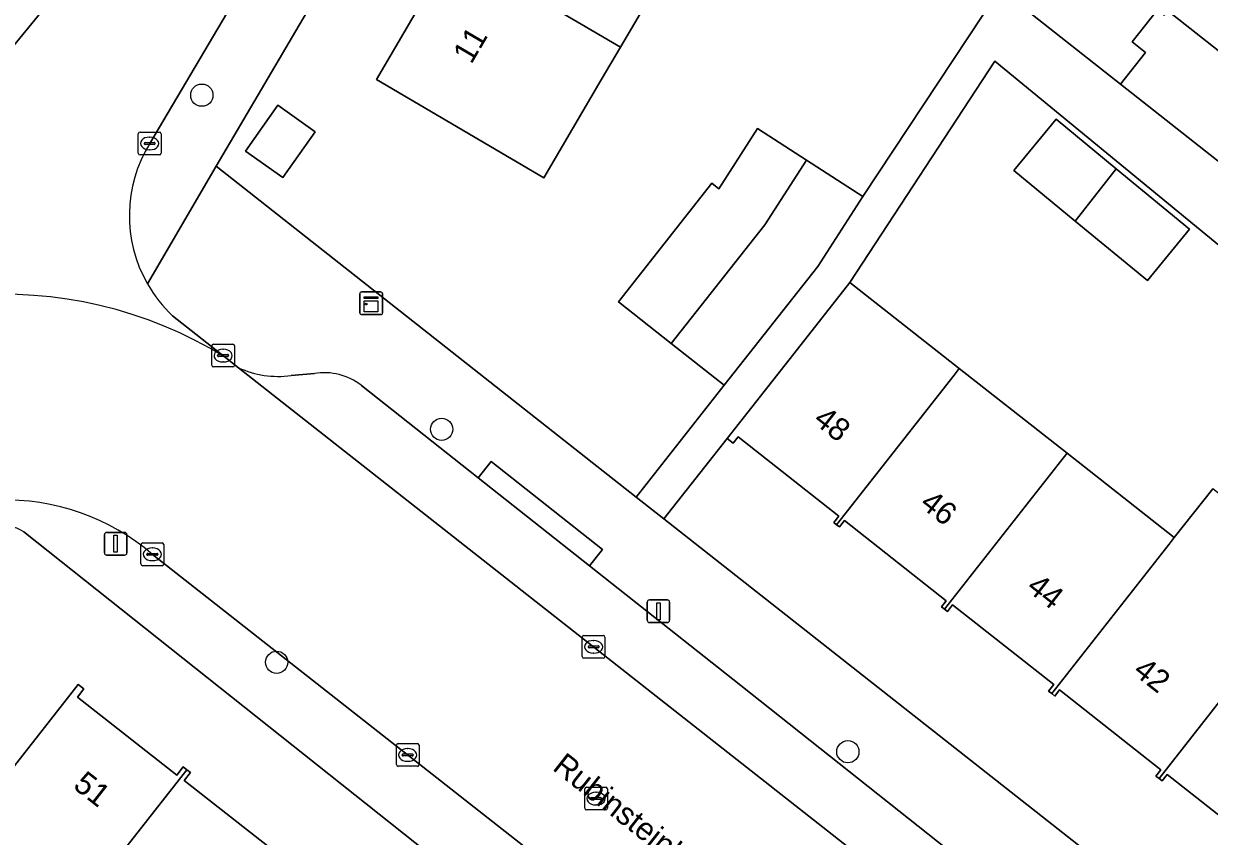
# Model space of a CAD drawing. Extents: x 159217 to 160349, y 381246 to 382172.
# Drawn here: x 160092 to 160144.2, y 381952.3 to 381988.1 of the extents above; entities that cross this region are included whole.
import ezdxf

# ---------------------------------------------------------------- set-up
doc = ezdxf.new("R2010")
doc.units = 0
for name, color, linetype in [('IMGEO_Boom', 7, 'Continuous'), ('IMGEO_Erf', 7, 'Continuous'), ('IMGEO_Kast', 7, 'Continuous'), ('IMGEO_Kolk', 7, 'Continuous'), ('IMGEO_Lichtmast', 7, 'Continuous'), ('IMGEO_Openbare_ruimte_label', 7, 'Continuous'), ('IMGEO_Pand', 7, 'Continuous'), ('IMGEO_Pand_nummerreeks', 7, 'Continuous'), ('IMGEO_Parkeervlak_open', 7, 'Continuous'), ('IMGEO_Rijbaan_lokaal_gesloten', 7, 'Continuous'), ('IMGEO_Rijbaan_lokaal_open', 7, 'Continuous'), ('IMGEO_Rioolput', 7, 'Continuous'), ('IMGEO_Voetpad_open', 7, 'Continuous')]:
    doc.layers.add(name, color=color, linetype=linetype)

msp = doc.modelspace()

# ---------------------------------------------------------------- linework, layer by layer
at = {"layer": 'IMGEO_Boom'}
for centre in [(160099.826, 381984.911), (160110.381, 381970.206), (160103.116, 381959.953), (160128.263, 381956.012)]:
    msp.add_circle(centre, 0.489, dxfattribs=at)
at = {"layer": 'IMGEO_Erf'}
for points in [[(160126.924, 382026.759), (160111.174, 382000), (160100.451, 381981.781), (160118.948, 381967.225), (160122.82, 381972.146), (160120.49, 381973.98), (160118.16, 381975.813), (160122.273, 381981.04), (160122.583, 381980.796), (160124.283, 381983.444), (160126.436, 381982.056), (160128.915, 381980.458), (160134.234, 381988.47), (160134.467, 381988.841), (160132.014, 381990.384), (160133.701, 381993.064), (160135.459, 381995.859)], [(160142.347, 381988.629), (160147.34, 381984.688)], [(160146.891, 381976.411), (160134.736, 381986.411), (160128.352, 381976.673), (160133.167, 381972.884), (160137.909, 381969.152), (160142.626, 381965.44), (160144.323, 381967.591)], [(160146.725, 381951.543), (160142.32, 381955.01), (160142.097, 381954.727), (160141.958, 381954.836), (160141.822, 381954.943), (160142.04, 381955.219), (160137.577, 381958.731), (160137.369, 381958.466), (160137.235, 381958.572), (160137.099, 381958.679), (160137.326, 381958.967), (160132.872, 381962.473), (160132.647, 381962.186), (160132.516, 381962.289), (160132.386, 381962.392), (160132.595, 381962.658), (160128.11, 381966.187), (160127.889, 381965.907), (160127.765, 381966.005), (160127.639, 381966.104), (160127.86, 381966.385), (160123.434, 381969.867), (160123.219, 381969.593), (160122.949, 381969.806), (160120.164, 381966.268), (160212.178, 381893.858)], [(160135.047, 381931.474), (160091.985, 381965.697)], [(160087.516, 381950.232), (160089.231, 381952.418), (160094.379, 381958.975)], [(160094.379, 381958.975), (160094.63, 381958.778), (160094.351, 381958.422), (160098.729, 381954.986), (160099.01, 381955.344), (160099.168, 381955.22), (160099.323, 381955.098), (160099.05, 381954.749), (160103.465, 381951.284)]]:
    msp.add_lwpolyline(points, dxfattribs=at)
for points in [[(160118.255, 381987.024), (160117.408, 381985.582), (160114.88, 381981.268), (160107.512, 381985.605), (160110.881, 381991.35), (160114.176, 381996.967), (160115.955, 382000), (160117.471, 382002.584), (160120.765, 382008.2), (160124.08, 382013.852), (160127.432, 382019.567), (160131.914, 382016.929), (160133.752, 382020.052), (160139.591, 382015.557), (160137.882, 382012.653), (160134.482, 382014.654), (160131.509, 382009.591), (160128.149, 382003.87), (160125.876, 382000), (160124.851, 381998.255), (160121.553, 381992.64)], [(160103.394, 381981.281), (160101.747, 381982.443), (160103.174, 381984.466), (160104.821, 381983.304)], [(160135.57, 381981.592), (160137.425, 381983.849), (160140.075, 381981.67), (160143.306, 381979.014), (160141.45, 381976.758), (160138.27, 381979.372)]]:
    msp.add_lwpolyline(points, close=True, dxfattribs=at)
msp.add_arc((160090.828, 381963.741), 2.273, 59.4048, 126.484, dxfattribs=at)
at = {"layer": 'IMGEO_Kast'}
for p, q in [((160106.779, 381975.327), (160106.779, 381976.168)), ((160106.779, 381976.168), (160106.779, 381975.327)), ((160106.854, 381976.252), (160107.695, 381976.252)), ((160107.695, 381976.252), (160106.854, 381976.252)), ((160107.779, 381976.177), (160107.779, 381975.336)), ((160107.779, 381975.336), (160107.779, 381976.177)), ((160107.704, 381975.252), (160106.863, 381975.252)), ((160106.863, 381975.252), (160107.704, 381975.252))]:
    msp.add_line(p, q, dxfattribs=at)
for points in [[(160106.974, 381976.042), (160107.574, 381976.042), (160107.574, 381975.957), (160106.974, 381975.957), (160106.974, 381976.042)], [(160106.974, 381975.867), (160107.574, 381975.867), (160107.574, 381975.378), (160106.974, 381975.378), (160106.974, 381975.867)]]:
    msp.add_lwpolyline(points, dxfattribs=at)
msp.add_circle((160107.058, 381975.716), 0.0377, dxfattribs=at)
for centre, start, end in [((160106.857, 381976.174), 92.4484, 184.2845), ((160106.857, 381976.174), 92.4484, 184.2845), ((160107.701, 381976.174), 2.4484, 94.2845), ((160107.701, 381976.174), 2.4484, 94.2845), ((160106.857, 381975.33), 182.4484, 274.2845), ((160106.857, 381975.33), 182.4484, 274.2845), ((160107.701, 381975.33), 272.4484, 4.2845), ((160107.701, 381975.33), 272.4484, 4.2845)]:
    msp.add_arc(centre, 0.0779, start, end, dxfattribs=at)
at = {"layer": 'IMGEO_Kolk'}
for p, q in [((160097.029, 381982.358), (160097.029, 381983.21)), ((160097.104, 381983.284), (160097.956, 381983.284)), ((160097.517, 381983.064), (160097.542, 381983.064)), ((160098.03, 381983.21), (160098.03, 381982.358)), ((160097.288, 381982.778), (160097.288, 381982.79)), ((160097.726, 381982.741), (160097.328, 381982.741)), ((160097.331, 381982.827), (160097.729, 381982.827)), ((160097.54, 381982.504), (160097.515, 381982.504)), ((160097.772, 381982.79), (160097.772, 381982.778)), ((160097.956, 381982.284), (160097.104, 381982.284)), ((160100.263, 381973.023), (160100.263, 381973.875)), ((160100.338, 381973.949), (160101.19, 381973.949)), ((160100.565, 381973.492), (160100.963, 381973.492)), ((160100.751, 381973.729), (160100.776, 381973.729)), ((160101.264, 381973.875), (160101.264, 381973.023)), ((160100.522, 381973.443), (160100.522, 381973.455)), ((160100.96, 381973.406), (160100.562, 381973.406)), ((160100.774, 381973.169), (160100.749, 381973.169)), ((160101.006, 381973.455), (160101.006, 381973.443)), ((160101.19, 381972.949), (160100.338, 381972.949)), ((160097.147, 381964.277), (160097.147, 381965.129)), ((160097.222, 381965.203), (160098.074, 381965.203)), ((160098.148, 381965.129), (160098.148, 381964.277)), ((160097.406, 381964.697), (160097.406, 381964.709)), ((160097.844, 381964.66), (160097.446, 381964.66)), ((160097.449, 381964.746), (160097.847, 381964.746)), ((160097.635, 381964.983), (160097.66, 381964.983)), ((160097.89, 381964.709), (160097.89, 381964.697)), ((160098.074, 381964.203), (160097.222, 381964.203)), ((160097.658, 381964.423), (160097.633, 381964.423)), ((160116.57, 381960.204), (160116.57, 381961.056)), ((160116.645, 381961.13), (160117.497, 381961.13)), ((160117.571, 381961.056), (160117.571, 381960.204)), ((160116.829, 381960.624), (160116.829, 381960.636)), ((160117.267, 381960.587), (160116.869, 381960.587)), ((160116.872, 381960.673), (160117.27, 381960.673)), ((160117.058, 381960.91), (160117.083, 381960.91)), ((160117.313, 381960.636), (160117.313, 381960.624)), ((160117.497, 381960.13), (160116.645, 381960.13)), ((160117.081, 381960.35), (160117.056, 381960.35)), ((160108.387, 381955.445), (160108.387, 381956.297)), ((160108.462, 381956.371), (160109.314, 381956.371)), ((160109.388, 381956.297), (160109.388, 381955.445)), ((160108.646, 381955.865), (160108.646, 381955.877)), ((160109.084, 381955.828), (160108.686, 381955.828)), ((160108.689, 381955.914), (160109.087, 381955.914)), ((160108.875, 381956.151), (160108.9, 381956.151)), ((160109.13, 381955.877), (160109.13, 381955.865)), ((160109.314, 381955.371), (160108.462, 381955.371)), ((160108.898, 381955.591), (160108.873, 381955.591))]:
    msp.add_line(p, q, dxfattribs=at)
for points in [[(160097.029, 381982.358), (160097.029, 381983.21)], [(160097.104, 381983.284), (160097.956, 381983.284)], [(160098.03, 381983.21), (160098.03, 381982.358)], [(160097.956, 381982.284), (160097.104, 381982.284)], [(160100.263, 381973.023), (160100.263, 381973.875)], [(160100.338, 381973.949), (160101.19, 381973.949)], [(160101.264, 381973.875), (160101.264, 381973.023)], [(160101.19, 381972.949), (160100.338, 381972.949)], [(160097.147, 381964.277), (160097.147, 381965.129)], [(160097.222, 381965.203), (160098.074, 381965.203)], [(160098.148, 381965.129), (160098.148, 381964.277)], [(160098.074, 381964.203), (160097.222, 381964.203)], [(160116.57, 381960.204), (160116.57, 381961.056)], [(160116.645, 381961.13), (160117.497, 381961.13)], [(160117.571, 381961.056), (160117.571, 381960.204)], [(160117.497, 381960.13), (160116.645, 381960.13)], [(160108.387, 381955.445), (160108.387, 381956.297)], [(160108.462, 381956.371), (160109.314, 381956.371)], [(160109.388, 381956.297), (160109.388, 381955.445)], [(160109.314, 381955.371), (160108.462, 381955.371)]]:
    msp.add_lwpolyline(points, dxfattribs=at)
for centre, radius, start, end in [((160097.106, 381983.208), 0.0765, 91.552, 178.448), ((160097.106, 381983.208), 0.0765, 91.552, 178.448), ((160097.954, 381983.208), 0.0765, 1.552, 88.448), ((160097.954, 381983.208), 0.0765, 1.552, 88.448), ((160097.106, 381982.36), 0.0765, 181.552, 268.448), ((160097.106, 381982.36), 0.0765, 181.552, 268.448), ((160097.328, 381982.787), 0.0403, 85.8775, 175.7526), ((160097.325, 381982.777), 0.0366, 178.938, 274.7102), ((160097.729, 381982.784), 0.043, 264.8664, 352.4533), ((160097.733, 381982.789), 0.0386, 1.7309, 96.639), ((160097.954, 381982.36), 0.0765, 271.552, 358.448), ((160097.954, 381982.36), 0.0765, 271.552, 358.448), ((160100.34, 381973.873), 0.0765, 91.552, 178.448), ((160100.34, 381973.873), 0.0765, 91.552, 178.448), ((160100.562, 381973.452), 0.0403, 85.8775, 175.7526), ((160100.967, 381973.454), 0.0386, 1.7309, 96.639), ((160101.188, 381973.873), 0.0765, 1.552, 88.448), ((160101.188, 381973.873), 0.0765, 1.552, 88.448), ((160100.34, 381973.025), 0.0765, 181.552, 268.448), ((160100.34, 381973.025), 0.0765, 181.552, 268.448), ((160100.559, 381973.442), 0.0366, 178.938, 274.7102), ((160100.963, 381973.449), 0.043, 264.8664, 352.4533), ((160101.188, 381973.025), 0.0765, 271.552, 358.448), ((160101.188, 381973.025), 0.0765, 271.552, 358.448), ((160097.224, 381965.127), 0.0765, 91.552, 178.448), ((160097.224, 381965.127), 0.0765, 91.552, 178.448), ((160098.072, 381965.127), 0.0765, 1.552, 88.448), ((160098.072, 381965.127), 0.0765, 1.552, 88.448), ((160097.446, 381964.706), 0.0403, 85.8775, 175.7526), ((160097.443, 381964.696), 0.0366, 178.938, 274.7102), ((160097.847, 381964.703), 0.043, 264.8664, 352.4533), ((160097.851, 381964.708), 0.0386, 1.7309, 96.639), ((160097.224, 381964.279), 0.0765, 181.552, 268.448), ((160097.224, 381964.279), 0.0765, 181.552, 268.448), ((160098.072, 381964.279), 0.0765, 271.552, 358.448), ((160098.072, 381964.279), 0.0765, 271.552, 358.448), ((160116.647, 381961.054), 0.0765, 91.552, 178.448), ((160116.647, 381961.054), 0.0765, 91.552, 178.448), ((160117.495, 381961.054), 0.0765, 1.552, 88.448), ((160117.495, 381961.054), 0.0765, 1.552, 88.448), ((160116.869, 381960.633), 0.0403, 85.8775, 175.7526), ((160116.866, 381960.623), 0.0366, 178.938, 274.7102), ((160117.27, 381960.63), 0.043, 264.8664, 352.4533), ((160117.274, 381960.635), 0.0386, 1.7309, 96.639), ((160116.647, 381960.206), 0.0765, 181.552, 268.448), ((160116.647, 381960.206), 0.0765, 181.552, 268.448), ((160117.495, 381960.206), 0.0765, 271.552, 358.448), ((160117.495, 381960.206), 0.0765, 271.552, 358.448), ((160108.464, 381956.295), 0.0765, 91.552, 178.448), ((160108.464, 381956.295), 0.0765, 91.552, 178.448), ((160109.312, 381956.295), 0.0765, 1.552, 88.448), ((160109.312, 381956.295), 0.0765, 1.552, 88.448), ((160108.686, 381955.874), 0.0403, 85.8775, 175.7526), ((160108.683, 381955.864), 0.0366, 178.938, 274.7102), ((160109.087, 381955.871), 0.043, 264.8664, 352.4533), ((160109.091, 381955.876), 0.0386, 1.7309, 96.639), ((160108.464, 381955.447), 0.0765, 181.552, 268.448), ((160108.464, 381955.447), 0.0765, 181.552, 268.448), ((160109.312, 381955.447), 0.0765, 271.552, 358.448), ((160109.312, 381955.447), 0.0765, 271.552, 358.448)]:
    msp.add_arc(centre, radius, start, end, dxfattribs=at)
for centre, major_axis, ratio, start_param, end_param in [((160097.516, 381982.784), (-0.387, 0.002), 0.722429, 4.712389, 7.853982), ((160097.541, 381982.784), (-0.39, 0.002), 0.717154, 1.570796, 4.712389), ((160100.75, 381973.449), (-0.387, 0.002), 0.722429, 4.712389, 7.853982), ((160100.775, 381973.449), (-0.39, 0.002), 0.717154, 1.570796, 4.712389), ((160097.634, 381964.703), (-0.387, 0.002), 0.722429, 4.712389, 7.853982), ((160097.659, 381964.703), (-0.39, 0.002), 0.717154, 1.570796, 4.712389), ((160117.057, 381960.63), (-0.387, 0.002), 0.722429, 4.712389, 7.853982), ((160117.082, 381960.63), (-0.39, 0.002), 0.717154, 1.570796, 4.712389), ((160108.874, 381955.871), (-0.387, 0.002), 0.722429, 4.712389, 7.853982), ((160108.899, 381955.871), (-0.39, 0.002), 0.717154, 1.570796, 4.712389)]:
    msp.add_ellipse(centre, major_axis=major_axis, ratio=ratio, start_param=start_param, end_param=end_param, dxfattribs=at)
at = {"layer": 'IMGEO_Lichtmast'}
for p, q in [((160095.636, 381965.669), (160096.426, 381965.669)), ((160096.426, 381965.669), (160095.636, 381965.669)), ((160095.536, 381964.769), (160095.536, 381965.569)), ((160095.536, 381965.569), (160095.536, 381964.769)), ((160096.526, 381965.569), (160096.526, 381964.769)), ((160096.526, 381964.769), (160096.526, 381965.569)), ((160096.426, 381964.669), (160095.636, 381964.669)), ((160095.636, 381964.669), (160096.426, 381964.669)), ((160119.428, 381961.799), (160119.428, 381962.599)), ((160119.428, 381962.599), (160119.428, 381961.799)), ((160119.528, 381962.699), (160120.318, 381962.699)), ((160120.318, 381962.699), (160119.528, 381962.699)), ((160120.418, 381962.599), (160120.418, 381961.799)), ((160120.418, 381961.799), (160120.418, 381962.599)), ((160120.318, 381961.699), (160119.528, 381961.699)), ((160119.528, 381961.699), (160120.318, 381961.699))]:
    msp.add_line(p, q, dxfattribs=at)
for points in [[(160095.956, 381965.544), (160096.106, 381965.544), (160096.106, 381964.794), (160095.956, 381964.794), (160095.956, 381965.544)], [(160119.848, 381962.574), (160119.998, 381962.574), (160119.998, 381961.824), (160119.848, 381961.824), (160119.848, 381962.574)]]:
    msp.add_lwpolyline(points, dxfattribs=at)
for centre, start, end in [((160095.636, 381965.569), 90, 180), ((160095.636, 381965.569), 90, 180), ((160096.426, 381965.569), 0, 90), ((160096.426, 381965.569), 360, 90), ((160095.636, 381964.769), 180, 270), ((160095.636, 381964.769), 180, 270), ((160096.426, 381964.769), 270, 0), ((160096.426, 381964.769), 270, 0), ((160119.528, 381962.599), 90, 180), ((160119.528, 381962.599), 90, 180), ((160120.318, 381962.599), 0, 90), ((160120.318, 381962.599), 360, 90), ((160119.528, 381961.799), 180, 270), ((160119.528, 381961.799), 180, 270), ((160120.318, 381961.799), 270, 0), ((160120.318, 381961.799), 270, 0)]:
    msp.add_arc(centre, 0.1, start, end, dxfattribs=at)
at = {"layer": 'IMGEO_Pand'}
for points in [[(160118.255, 381987.024), (160121.553, 381992.64), (160114.176, 381996.967), (160110.881, 381991.35)], [(160140.263, 381985.397), (160141.368, 381986.793), (160140.78, 381987.259), (160141.89, 381988.662), (160142.184, 381988.429), (160142.347, 381988.629), (160142.24, 381988.714), (160142.971, 381989.64), (160138.933, 381992.828), (160136.182, 381988.616)], [(160118.255, 381987.024), (160110.881, 381991.35), (160107.512, 381985.605), (160114.88, 381981.268), (160117.408, 381985.582)], [(160140.263, 381985.397), (160144.969, 381981.684), (160147.34, 381984.688), (160142.347, 381988.629), (160142.184, 381988.429), (160141.89, 381988.662), (160140.78, 381987.259), (160141.368, 381986.793)], [(160101.747, 381982.443), (160103.394, 381981.281), (160104.821, 381983.304), (160103.174, 381984.466)], [(160124.605, 381979.205), (160126.436, 381982.056), (160124.283, 381983.444), (160122.583, 381980.796), (160122.273, 381981.04), (160118.16, 381975.813), (160120.49, 381973.98)], [(160140.075, 381981.67), (160137.425, 381983.849), (160135.57, 381981.592), (160138.27, 381979.372)], [(160120.49, 381973.98), (160122.82, 381972.146), (160126.933, 381977.373), (160128.915, 381980.458), (160126.436, 381982.056), (160124.605, 381979.205)], [(160140.075, 381981.67), (160138.27, 381979.372), (160141.45, 381976.758), (160143.306, 381979.014)], [(160127.765, 381966.005), (160132.935, 381972.584), (160133.167, 381972.884), (160128.352, 381976.673), (160126.041, 381973.736), (160122.949, 381969.806), (160123.219, 381969.593), (160123.434, 381969.867), (160127.86, 381966.385), (160127.639, 381966.104)], [(160137.909, 381969.152), (160133.167, 381972.884), (160132.935, 381972.584), (160127.765, 381966.005), (160127.889, 381965.907), (160128.11, 381966.187), (160132.595, 381962.658), (160132.386, 381962.392), (160132.516, 381962.289), (160137.678, 381968.858)], [(160137.235, 381958.572), (160142.401, 381965.146), (160142.626, 381965.44), (160137.909, 381969.152), (160137.678, 381968.858), (160132.516, 381962.289), (160132.647, 381962.186), (160132.872, 381962.473), (160137.326, 381958.967), (160137.099, 381958.679)], [(160147.362, 381961.713), (160149.055, 381963.867), (160144.323, 381967.591), (160142.626, 381965.44), (160142.401, 381965.146), (160137.235, 381958.572), (160137.369, 381958.466), (160137.577, 381958.731), (160142.04, 381955.219), (160141.822, 381954.943), (160141.958, 381954.836), (160147.136, 381961.425)], [(160146.688, 381951.208), (160151.823, 381957.742), (160152.042, 381958.03), (160147.362, 381961.713), (160147.136, 381961.425), (160141.958, 381954.836), (160142.097, 381954.727), (160142.32, 381955.01), (160146.725, 381951.543), (160146.548, 381951.317)], [(160099.168, 381955.22), (160099.01, 381955.344), (160098.729, 381954.986), (160094.351, 381958.422), (160094.63, 381958.778), (160094.379, 381958.975), (160089.231, 381952.418), (160087.516, 381950.232), (160092.439, 381946.368), (160092.777, 381946.798), (160094.155, 381948.553), (160094.014, 381948.664)], [(160103.903, 381951.502), (160103.738, 381951.631), (160103.465, 381951.284), (160099.05, 381954.749), (160099.323, 381955.098), (160099.168, 381955.22), (160094.014, 381948.664), (160094.155, 381948.553), (160096.118, 381947.005), (160098.745, 381944.942)]]:
    msp.add_lwpolyline(points, close=True, dxfattribs=at)
at = {"layer": 'IMGEO_Parkeervlak_open'}
for points in [[(160073.897, 381966.186), (160078.769, 381971.536), (160080.165, 381973.156), (160091.288, 381986.771), (160092.735, 381988.55), (160093.651, 381990.018), (160095.866, 381993.522), (160099.605, 381999.423), (160099.946, 382000), (160103.576, 382006.134), (160109.332, 382015.99), (160113.534, 382023.07), (160117.244, 382029.491), (160119.219, 382032.966), (160121.556, 382037.261), (160122.268, 382038.501)], [(160101.441, 381972.915), (160142.8, 381940.403), (160158.477, 381928.078), (160209.032, 381888.323), (160209.912, 381887.8)], [(160104.78, 381972.662), (160103.752, 381972.57)], [(160116.887, 381964.196), (160111.993, 381968.07), (160106.851, 381972.132)], [(160207.982, 381892.133), (160193.834, 381903.352), (160176.929, 381916.708), (160168.874, 381923.038), (160159.725, 381930.297), (160141.712, 381944.521), (160123.544, 381958.928), (160116.887, 381964.196)]]:
    msp.add_lwpolyline(points, dxfattribs=at)
for centre, radius, start, end in [((160103.194, 381976.744), 4.211, 245.4005, 277.618), ((160105.21, 381970.031), 2.666, 52.0122, 99.2783)]:
    msp.add_arc(centre, radius, start, end, dxfattribs=at)
at = {"layer": 'IMGEO_Rijbaan_lokaal_gesloten'}
for points in [[(160101.441, 381972.915), (160100.863, 381973.37)], [(160097.652, 381964.702), (160137.256, 381933.585), (160137.357, 381933.503), (160142.8, 381940.403), (160101.441, 381972.915)]]:
    msp.add_lwpolyline(points, dxfattribs=at)
for centre, radius, start, end in [((160091.059, 381957.479), 18.672, 58.3268, 131.1635), ((160091.212, 381957.21), 9.879, 49.318, 92.0711)]:
    msp.add_arc(centre, radius, start, end, dxfattribs=at)
at = {"layer": 'IMGEO_Rijbaan_lokaal_open'}
for points in [[(160125.51, 382029.203), (160127.869, 382033.644), (160130.339, 382038.678), (160132.186, 382043.112), (160123.708, 382041.592), (160123.283, 382040.403), (160122.754, 382039.257), (160122.435, 382038.719), (160122.268, 382038.501), (160121.556, 382037.261), (160119.219, 382032.966), (160117.244, 382029.491), (160113.534, 382023.07), (160109.332, 382015.99), (160103.576, 382006.134), (160099.946, 382000), (160099.605, 381999.423), (160095.866, 381993.522), (160093.651, 381990.018), (160092.735, 381988.55), (160091.288, 381986.771), (160080.165, 381973.156), (160078.769, 381971.536)], [(160097.531, 381982.788), (160107.711, 382000), (160124.728, 382028.051)], [(160100.863, 381973.37), (160098.535, 381975.2)]]:
    msp.add_lwpolyline(points, dxfattribs=at)
for centre, radius, start, end in [((160102.704, 381979.612), 6.07, 148.4481, 209.6799), ((160091.059, 381957.479), 18.672, 58.3268, 131.1635), ((160102.731, 381979.635), 6.105, 209.7433, 226.5855)]:
    msp.add_arc(centre, radius, start, end, dxfattribs=at)
at = {"layer": 'IMGEO_Rioolput'}
for p, q in [((160116.679, 381953.524), (160116.679, 381954.376)), ((160116.754, 381954.45), (160117.606, 381954.45)), ((160117.167, 381954.23), (160117.192, 381954.23)), ((160117.68, 381954.376), (160117.68, 381953.524)), ((160116.938, 381953.944), (160116.938, 381953.956)), ((160117.376, 381953.907), (160116.978, 381953.907)), ((160116.981, 381953.993), (160117.379, 381953.993)), ((160117.19, 381953.67), (160117.165, 381953.67)), ((160117.422, 381953.956), (160117.422, 381953.944)), ((160117.606, 381953.45), (160116.754, 381953.45))]:
    msp.add_line(p, q, dxfattribs=at)
for points in [[(160116.679, 381953.524), (160116.679, 381954.376)], [(160116.754, 381954.45), (160117.606, 381954.45)], [(160117.68, 381954.376), (160117.68, 381953.524)], [(160117.606, 381953.45), (160116.754, 381953.45)]]:
    msp.add_lwpolyline(points, dxfattribs=at)
for centre, radius, start, end in [((160116.756, 381954.374), 0.0765, 91.552, 178.448), ((160116.756, 381954.374), 0.0765, 91.552, 178.448), ((160117.604, 381954.374), 0.0765, 1.552, 88.448), ((160117.604, 381954.374), 0.0765, 1.552, 88.448), ((160116.978, 381953.953), 0.0403, 85.8775, 175.7526), ((160116.975, 381953.943), 0.0366, 178.938, 274.7102), ((160117.379, 381953.95), 0.043, 264.8664, 352.4533), ((160117.383, 381953.955), 0.0386, 1.7309, 96.639), ((160116.756, 381953.526), 0.0765, 181.552, 268.448), ((160116.756, 381953.526), 0.0765, 181.552, 268.448), ((160117.604, 381953.526), 0.0765, 271.552, 358.448), ((160117.604, 381953.526), 0.0765, 271.552, 358.448)]:
    msp.add_arc(centre, radius, start, end, dxfattribs=at)
for centre, major_axis, ratio, start_param, end_param in [((160117.166, 381953.95), (-0.387, 0.002), 0.722429, 4.712389, 7.853982), ((160117.191, 381953.95), (-0.39, 0.002), 0.717154, 1.570796, 4.712389)]:
    msp.add_ellipse(centre, major_axis=major_axis, ratio=ratio, start_param=start_param, end_param=end_param, dxfattribs=at)
at = {"layer": 'IMGEO_Voetpad_open'}
for points in [[(160124.728, 382028.051), (160107.711, 382000), (160097.531, 381982.788)], [(160097.43, 381976.606), (160100.451, 381981.781), (160111.174, 382000), (160126.924, 382026.759)], [(160144.969, 381981.684), (160140.263, 381985.397), (160136.182, 381988.616)], [(160134.234, 381988.47), (160128.915, 381980.458), (160126.933, 381977.373), (160122.82, 381972.146), (160118.948, 381967.225), (160120.164, 381966.268), (160122.949, 381969.806), (160126.041, 381973.736), (160128.352, 381976.673), (160134.736, 381986.411), (160146.891, 381976.411)], [(160212.838, 381893.504), (160212.178, 381893.858), (160120.164, 381966.268), (160118.948, 381967.225), (160100.451, 381981.781), (160097.43, 381976.606)], [(160098.535, 381975.2), (160100.863, 381973.37), (160101.441, 381972.915)], [(160103.752, 381972.57), (160104.78, 381972.662)], [(160106.851, 381972.132), (160111.993, 381968.07), (160112.566, 381968.792), (160117.457, 381964.915), (160116.887, 381964.196), (160123.544, 381958.928), (160141.712, 381944.521), (160159.725, 381930.297), (160168.874, 381923.038), (160176.929, 381916.708), (160193.834, 381903.352), (160207.982, 381892.133)], [(160091.985, 381965.697), (160135.047, 381931.474)], [(160137.357, 381933.503), (160137.256, 381933.585), (160097.652, 381964.702)]]:
    msp.add_lwpolyline(points, dxfattribs=at)
msp.add_lwpolyline([(160112.566, 381968.792), (160111.993, 381968.07), (160116.887, 381964.196), (160117.457, 381964.915)], close=True, dxfattribs=at)
for centre, radius, start, end in [((160102.704, 381979.612), 6.07, 148.4481, 209.6799), ((160102.731, 381979.635), 6.105, 209.7433, 226.5855), ((160103.194, 381976.744), 4.211, 245.4005, 277.618), ((160105.21, 381970.031), 2.666, 52.0122, 99.2783), ((160091.212, 381957.21), 9.879, 49.318, 92.0711), ((160090.828, 381963.741), 2.273, 59.4048, 126.484)]:
    msp.add_arc(centre, radius, start, end, dxfattribs=at)

# ---------------------------------------------------------------- texts
at = {"layer": 'IMGEO_Openbare_ruimte_label'}
msp.add_text('Rubinsteinlaan', height=1, rotation=321.8235, dxfattribs=at).set_placement((160115.215, 381955.245))
at = {"layer": 'IMGEO_Pand_nummerreeks'}
for s, rotation, p in [('11', 59.6068, (160111.686, 381986.24)), ('48', 321.8608, (160126.69, 381970.514)), ('46', 321.8608, (160131.381, 381966.83)), ('44', 321.8608, (160136.074, 381963.145)), ('42', 321.8582, (160140.766, 381959.461)), ('51', 321.9098, (160094.111, 381954.442))]:
    msp.add_text(s, height=1, rotation=rotation, dxfattribs=at).set_placement(p)

doc.saveas('drawing.dxf')
